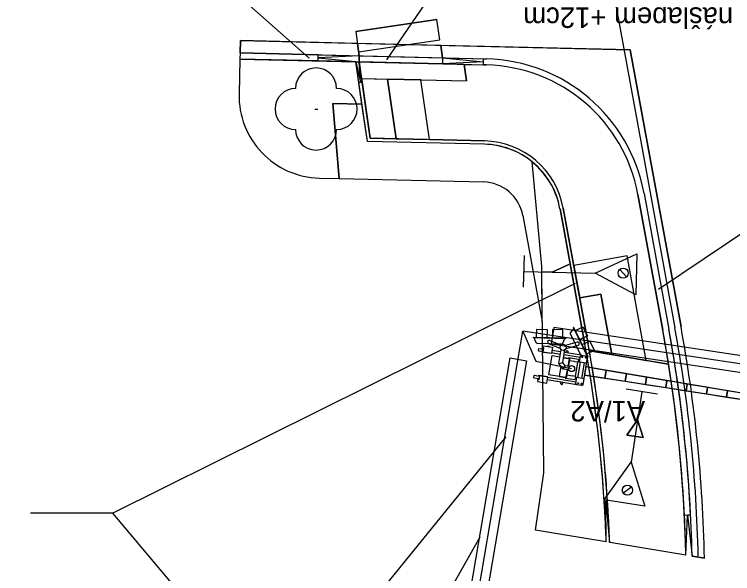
# Model space of a CAD drawing. Extents: x -728547 to -728179, y -1073068 to -1072839.
# Drawn here: x -728526.3 to -728508.81, y -1073041.79 to -1073028.16 of the extents above; entities that cross this region are included whole.
import ezdxf

# ---------------------------------------------------------------- set-up
doc = ezdxf.new("R2010")
doc.units = 0
for name, color, linetype in [('_NOR-návrh tenká', 7, 'Continuous'), ('_NOR-popis', 7, 'Continuous'), ('_NOR-VDZ', 7, 'Continuous'), ('_NOR-zrušit', 7, 'Continuous'), ('_NOR-šraf_+12', 7, 'Continuous'), ('_NOR-šraf_+6', 7, 'Continuous'), ('_NOR-šraf_bezbariéra', 7, 'Continuous'), ('_NOR-šraf_chodník', 7, 'Continuous'), ('_NOR-šraf_signální pás', 7, 'Continuous'), ('_NOR-šraf_varovný pás', 7, 'Continuous'), ('_NOR-šraf_vozovka', 7, 'Continuous'), ('_NOR-šraf_zeleň', 7, 'Continuous'), ('KOS_kabelová trasa', 7, 'Continuous'), ('KOS_kabelová trasa popis', 7, 'Continuous'), ('KOS_nové prvky PZZ', 7, 'Continuous'), ('KTA_PZZ rušené', 7, 'Continuous')]:
    doc.layers.add(name, color=color, linetype=linetype)

# ---------------------------------------------------------------- blocks, each defined once
blk = doc.blocks.new('Závora A')
for p, q in [((0.395, 0.28), (0.046, 0.997)), ((-0.139, 0.725), (-0.935, 0.747)), ((-0.596, 0.546), (-0.597, 0.54)), ((-0.535, 0.536), (-0.596, 0.546)), ((-0.563, 0.613), (-0.27, 0.487)), ((0.138, 0.645), (-0.147, 0.563)), ((-0.697, 0.505), (-0.702, 0.477)), ((-0.277, 0.347), (-0.486, 0.381)), ((-0.268, 0.407), (-0.477, 0.44)), ((0.244, 0.323), (-0.178, 0.392)), ((0.209, 0.268), (-0.188, 0.333)), ((0.191, 0.16), (0.215, 0.304)), ((0.244, 0.323), (0.215, 0.304)), ((0.279, -0.392), (0.387, 0.276)), ((0.365, 0.304), (0.387, 0.276)), ((-0.313, 0.128), (-0.217, 0.151)), ((-0.292, -0.182), (-0.255, 0.051)), ((-0.207, -0.012), (-0.156, 0.07)), ((0.094, -0.192), (0.15, 0.154)), ((0.153, -0.224), (0.215, 0.156)), ((0.364, 0.132), (0.191, 0.16)), ((0.253, -0.24), (0.314, 0.14)), ((0.349, 0.041), (0.317, -0.157)), ((0.349, 0.041), (0.317, -0.157)), ((0.349, 0.041), (0.317, -0.157)), ((0.349, 0.041), (0.317, -0.157)), ((7.251, -1.126), (0.349, 0.041)), ((7.234, -1.232), (0.317, -0.157)), ((-0.822, -0.267), (-0.818, -0.239)), ((-0.739, -0.338), (-0.738, -0.331)), ((-0.679, -0.347), (-0.739, -0.338)), ((0.128, -0.392), (-0.593, -0.275)), ((0.112, -0.329), (-0.583, -0.216)), ((0.302, -0.248), (0.13, -0.22)), ((0.128, -0.392), (0.106, -0.365)), ((0.249, -0.412), (0.128, -0.392)), ((0.249, -0.412), (0.279, -0.392)), ((7.251, -1.126), (7.234, -1.232))]:
    blk.add_line(p, q)
for points in [[(-0.856, 0.758), (-0.85, 0.96), (-0.599, 0.953), (-0.605, 0.751)], [(-0.217, 0.74), (-0.212, 0.942), (-0.463, 0.949), (-0.468, 0.747)], [(0.381, 0.307), (0.259, 0.299), (0.234, 0.31), (-0.029, 0.85), (-0.025, 0.875), (0.058, 0.972)], [(0.395, 0.28), (0.407, 0.286), (0.058, 1.002), (0.046, 0.997)], [(0.092, 0.931), (0.274, 1.02), (0.384, 0.794), (0.202, 0.706)], [(-0.139, 0.725), (-0.138, 0.738), (-0.935, 0.76), (-0.935, 0.747)], [(-0.169, 0.725), (-0.218, 0.613), (-0.24, 0.597), (-0.84, 0.613), (-0.86, 0.628), (-0.908, 0.746)], [(-0.465, 0.518), (-0.488, 0.371), (-0.691, 0.404), (-0.675, 0.502), (-0.697, 0.505), (-0.689, 0.555), (-0.465, 0.518)], [(-0.549, 0.689), (-0.561, 0.687), (-0.575, 0.676), (-0.581, 0.66), (-0.584, 0.646), (-0.582, 0.633), (-0.575, 0.623), (-0.573, 0.62), (-0.569, 0.617), (-0.563, 0.613)], [(-0.577, 0.536), (-0.536, 0.53)], [(-0.549, 0.689), (-0.257, 0.571)], [(-0.535, 0.536), (-0.536, 0.53)], [(0.159, 0.566), (-0.143, 0.48)], [(0.159, 0.566), (0.178, 0.576), (0.185, 0.588), (0.188, 0.603), (0.188, 0.619), (0.183, 0.629), (0.174, 0.636), (0.16, 0.643), (0.148, 0.644), (0.138, 0.645)], [(0.372, 0.357), (0.554, 0.446), (0.444, 0.671), (0.262, 0.583)], [(-0.804, 0.493), (-0.812, 0.44), (-0.807, 0.432), (-0.69, 0.413)], [(-0.804, 0.493), (-0.68, 0.473)], [(-0.691, 0.404), (-0.714, 0.408), (-0.712, 0.417)], [(-0.492, 0.372), (-0.493, 0.364), (-0.691, 0.396), (-0.69, 0.404)], [(-0.078, -0.033), (-0.207, -0.012), (-0.313, 0.128), (-0.258, 0.467)], [(-0.058, 0.054), (-0.156, 0.07), (-0.217, 0.151), (-0.168, 0.455)], [(-0.111, 0.433), (-0.124, 0.435), (-0.126, 0.428), (-0.13, 0.429), (-0.132, 0.42), (-0.136, 0.42), (-0.139, 0.397), (-0.148, 0.399), (-0.149, 0.393), (-0.15, 0.387)], [(-0.111, 0.433), (-0.098, 0.431), (-0.098, 0.424), (-0.094, 0.423), (-0.095, 0.414), (-0.092, 0.413), (-0.095, 0.39), (-0.087, 0.389), (-0.088, 0.383), (-0.089, 0.377)], [(-0.3, -0.193), (-0.552, -0.152), (-0.475, 0.319), (-0.287, 0.289)], [(-0.199, 0.263), (-0.072, 0.243), (-0.068, 0.24), (-0.065, 0.237), (-0.062, 0.232), (-0.061, 0.226), (-0.088, 0.059)], [(-0.197, 0.274), (-0.069, 0.253), (-0.059, 0.249), (-0.054, 0.243), (-0.049, 0.235), (-0.048, 0.231), (-0.076, 0.057)], [(-0.074, 0.268), (0.169, 0.228), (0.158, 0.16), (0.15, 0.154), (0.067, 0.167), (0.068, 0.17), (-0.048, 0.188), (-0.048, 0.192), (-0.054, 0.193)], [(0.244, 0.323), (0.365, 0.304)], [(-0.259, 0.057), (-0.3, -0.193)], [(0.349, 0.041), (0.317, -0.157), (0.811, -0.234), (0.842, -0.043), (0.349, 0.041)], [(-0.92, -0.222), (-0.911, -0.169), (-0.904, -0.163), (-0.786, -0.182)], [(-0.606, -0.353), (-0.582, -0.206), (-0.785, -0.173), (-0.801, -0.271), (-0.822, -0.267), (-0.83, -0.316), (-0.606, -0.353)], [(-0.785, -0.173), (-0.807, -0.17), (-0.809, -0.179)], [(-0.586, -0.206), (-0.584, -0.198), (-0.782, -0.166), (-0.783, -0.173)], [(-0.294, -0.193), (-0.292, -0.182), (-0.145, -0.206), (-0.14, -0.205), (-0.136, -0.203), (-0.132, -0.199), (-0.129, -0.194), (-0.103, -0.029)], [(-0.294, -0.193), (-0.145, -0.218), (-0.135, -0.217), (-0.128, -0.212), (-0.121, -0.207), (-0.118, -0.203), (-0.09, -0.031)], [(-0.155, -0.23), (0.089, -0.269), (0.1, -0.201), (0.094, -0.192), (0.011, -0.179), (0.011, -0.181), (-0.104, -0.163), (-0.106, -0.166), (-0.112, -0.165)], [(0.842, -0.043), (0.811, -0.234), (1.305, -0.31), (1.335, -0.126), (0.842, -0.043)], [(1.828, -0.209), (1.335, -0.126), (1.305, -0.31), (1.799, -0.387), (1.828, -0.209)], [(-0.92, -0.222), (-0.796, -0.242)], [(-0.718, -0.335), (-0.678, -0.341)], [(-0.679, -0.347), (-0.678, -0.341)], [(-0.243, -0.384), (-0.256, -0.381), (-0.256, -0.375), (-0.261, -0.374), (-0.259, -0.365), (-0.263, -0.364), (-0.259, -0.341), (-0.268, -0.34), (-0.267, -0.334), (-0.266, -0.328)], [(-0.243, -0.384), (-0.23, -0.386), (-0.228, -0.379), (-0.224, -0.38), (-0.222, -0.37), (-0.219, -0.371), (-0.215, -0.348), (-0.206, -0.35), (-0.206, -0.344), (-0.205, -0.338)], [(0.106, -0.365), (0.13, -0.22)], [(1.828, -0.209), (1.799, -0.387), (2.293, -0.464), (2.321, -0.293), (1.828, -0.209)], [(2.321, -0.293), (2.293, -0.464), (2.787, -0.541), (2.814, -0.376), (2.321, -0.293)], [(2.814, -0.376), (2.787, -0.541), (3.282, -0.618), (3.307, -0.459), (2.814, -0.376)], [(3.8, -0.543), (3.307, -0.459), (3.282, -0.618), (3.776, -0.694), (3.8, -0.543)], [(3.8, -0.543), (3.776, -0.694), (4.27, -0.771), (4.293, -0.626), (3.8, -0.543)], [(4.293, -0.626), (4.27, -0.771), (4.764, -0.848), (4.786, -0.709), (4.293, -0.626)], [(4.786, -0.709), (4.764, -0.848), (5.258, -0.925), (5.279, -0.793), (4.786, -0.709)], [(5.279, -0.793), (5.258, -0.925), (5.752, -1.001), (5.772, -0.876), (5.279, -0.793)], [(5.772, -0.876), (5.752, -1.001), (6.246, -1.078), (6.265, -0.959), (5.772, -0.876)], [(6.758, -1.043), (6.265, -0.959), (6.246, -1.078), (6.74, -1.155), (6.758, -1.043)], [(7.234, -1.232), (7.251, -1.126), (6.758, -1.043), (6.74, -1.155), (7.234, -1.232)]]:
    blk.add_lwpolyline(points)
for centre, radius in [((-0.206, 0.518), 0.0735), ((0.261, 0.282), 0.0119), ((0.343, 0.268), 0.0119), ((0, 0), 0.0742), ((0.157, -0.358), 0.0119), ((0.24, -0.371), 0.0119)]:
    blk.add_circle(centre, radius)
blk = doc.blocks.new('C039_9')
blk.add_line((-0.071, 0), (0.071, 0))
for centre, start, end in [((-0.011, 1.002), 0, 180), ((-1.011, 0.002), 90, 270), ((0.989, 0.002), 270, 90), ((-0.011, -0.998), 180, 0)]:
    blk.add_arc(centre, 1, start, end)

msp = doc.modelspace()

# ---------------------------------------------------------------- linework, layer by layer
at = {"layer": '_NOR-návrh tenká'}
for p, q in [((-728520.806, -1073029.105), (-728520.81, -1073029.255)), ((-728518.907, -1073029.3), (-728518.904, -1073029.151)), ((-728517.904, -1073029.174), (-728518.905, -1073029.225)), ((-728518.905, -1073029.225), (-728517.908, -1073029.324)), ((-728517.904, -1073029.174), (-728517.908, -1073029.324)), ((-728515.876, -1073029.222), (-728515.879, -1073029.372)), ((-728515.876, -1073029.222), (-728514.878, -1073029.321)), ((-728514.88, -1073029.396), (-728514.876, -1073029.246)), ((-728517.989, -1073029.322), (-728517.875, -1073029.825)), ((-728517.875, -1073029.825), (-728517.908, -1073029.324)), ((-728514.878, -1073029.321), (-728515.879, -1073029.372)), ((-728515.347, -1073029.385), (-728515.288, -1073029.787)), ((-728517.002, -1073031.196), (-728517.215, -1073029.741)), ((-728516.191, -1073031.215), (-728516.404, -1073029.76)), ((-728517.835, -1073029.819), (-728517.914, -1073029.831)), ((-728511.381, -1073034.047), (-728512.679, -1073034.285)), ((-728510.914, -1073036.596), (-728511.381, -1073034.047)), ((-728512.024, -1073034.978), (-728512.535, -1073035.072)), ((-728511.753, -1073036.454), (-728512.024, -1073034.978)), ((-728512.299, -1073036.362), (-728510.368, -1073036.688)), ((-728512.227, -1073036.779), (-728510.305, -1073037.104)), ((-728512.056, -1073038.959), (-728512.056, -1073038.959)), ((-728511.856, -1073040.029), (-728511.936, -1073040.035)), ((-728511.888, -1073041.015), (-728511.896, -1073040.032)), ((-728511.896, -1073040.032), (-728511.808, -1073041.028)), ((-728509.834, -1073040.364), (-728509.984, -1073040.371)), ((-728509.948, -1073041.338), (-728509.909, -1073040.368)), ((-728509.909, -1073040.368), (-728509.797, -1073041.363))]:
    msp.add_line(p, q, dxfattribs=at)
for points in [[(-728520.806, -1073029.105), (-728520.799, -1073028.805), (-728511.304, -1073029.031), (-728510.067, -1073035.777)], [(-728520.81, -1073029.255), (-728514.811, -1073029.398)], [(-728520.806, -1073029.105), (-728514.808, -1073029.248)], [(-728514.857, -1073031.327), (-728517.706, -1073031.26), (-728517.989, -1073029.322)], [(-728514.855, -1073031.247), (-728517.636, -1073031.181), (-728517.908, -1073029.324)], [(-728517.849, -1073029.726), (-728515.288, -1073029.787)], [(-728511.116, -1073032.553), (-728510.51, -1073035.858)], [(-728510.968, -1073032.525), (-728510.362, -1073035.831)], [(-728512.408, -1073036.206), (-728513.014, -1073032.9)], [(-728512.33, -1073036.192), (-728512.935, -1073032.886)], [(-728509.496, -1073041.413), (-728509.797, -1073041.363)]]:
    msp.add_lwpolyline(points, dxfattribs=at)
for centre, radius, start, end in [((-728514.903, -1073033.247), 4, 10.3872, 88.6393), ((-728514.903, -1073033.247), 3.85, 10.3872, 88.6393), ((-728514.903, -1073033.247), 1.92, 10.3872, 88.6393), ((-728514.903, -1073033.247), 2, 10.3872, 88.6393), ((-728544.789, -1073042.142), 34.85, 1.3216, 10.3872), ((-728544.789, -1073042.142), 35, 1.2748, 10.3872), ((-728544.789, -1073042.142), 35.3, 1.1826, 10.3872), ((-728544.789, -1073042.142), 32.92, 1.9617, 10.3872), ((-728544.789, -1073042.142), 33, 1.9337, 10.3872)]:
    msp.add_arc(centre, radius, start, end, dxfattribs=at)
at = {"layer": '_NOR-popis'}
for p, q in [((-728517.231, -1073029.269), (-728511.028, -1073020.188)), ((-728522.769, -1073026.006), (-728519.122, -1073029.229)), ((-728500.781, -1073028.245), (-728510.615, -1073034.866)), ((-728523.91, -1073040.313), (-728512.641, -1073034.717)), ((-728523.91, -1073040.313), (-728525.91, -1073040.313)), ((-728523.91, -1073040.313), (-728515.463, -1073050.376))]:
    msp.add_line(p, q, dxfattribs=at)
at = {"layer": '_NOR-VDZ'}
for p, q in [((-728517.991, -1073028.58), (-728516.012, -1073028.291)), ((-728517.919, -1073029.075), (-728515.939, -1073028.786))]:
    msp.add_line(p, q, dxfattribs=at)
for points in [[(-728512.949, -1073020.89), (-728510.942, -1073031.839)], [(-728517.919, -1073029.075), (-728515.939, -1073028.786), (-728516.012, -1073028.291), (-728517.991, -1073028.58), (-728517.919, -1073029.075), (-728517.919, -1073029.075)], [(-728510.942, -1073031.839), (-728510.215, -1073035.804)]]:
    msp.add_lwpolyline(points, dxfattribs=at)
msp.add_arc((-728544.789, -1073042.142), 35.15, 1.2748, 10.3872, dxfattribs=at)
at = {"layer": '_NOR-šraf_+12'}
for points in [[(-728520.81, -1073029.255), (-728518.907, -1073029.3), (-728518.905, -1073029.225), (-728518.904, -1073029.151), (-728520.806, -1073029.105), (-728520.81, -1073029.255)], [(-728514.88, -1073029.396), (-728514.878, -1073029.321), (-728514.876, -1073029.246), (-728514.808, -1073029.248)], [(-728514.811, -1073029.398), (-728514.88, -1073029.396)], [(-728510.51, -1073035.858), (-728511.116, -1073032.553)], [(-728510.968, -1073032.525), (-728510.362, -1073035.831)], [(-728509.834, -1073040.364), (-728509.909, -1073040.368), (-728509.984, -1073040.371)]]:
    msp.add_lwpolyline(points, dxfattribs=at)
for centre, radius, start, end in [((-728514.903, -1073033.247), 4, 10.3872, 88.6393), ((-728514.903, -1073033.247), 3.85, 10.3872, 88.6393), ((-728544.789, -1073042.142), 34.85, 2.9119, 10.3872), ((-728544.789, -1073042.142), 35, 2.9119, 10.3872)]:
    msp.add_arc(centre, radius, start, end, dxfattribs=at)
at = {"layer": '_NOR-šraf_+6'}
for points in [[(-728517.989, -1073029.322), (-728517.875, -1073029.825), (-728517.908, -1073029.324), (-728517.849, -1073029.726), (-728517.835, -1073029.819), (-728517.636, -1073031.181), (-728517.002, -1073031.196), (-728516.191, -1073031.215), (-728514.855, -1073031.247)], [(-728514.857, -1073031.327), (-728517.706, -1073031.26), (-728517.989, -1073029.322)], [(-728512.408, -1073036.206), (-728513.014, -1073032.9)], [(-728512.935, -1073032.886), (-728512.33, -1073036.192)], [(-728511.856, -1073040.029), (-728511.936, -1073040.035)]]:
    msp.add_lwpolyline(points, dxfattribs=at)
for centre, radius, start, end in [((-728514.903, -1073033.247), 1.92, 10.3872, 88.6393), ((-728514.903, -1073033.247), 2, 10.3872, 88.6393), ((-728544.789, -1073042.142), 32.92, 3.67, 10.3872), ((-728544.789, -1073042.142), 33, 3.67, 10.3872)]:
    msp.add_arc(centre, radius, start, end, dxfattribs=at)
at = {"layer": '_NOR-šraf_bezbariéra'}
msp.add_lwpolyline([(-728517.904, -1073029.174), (-728515.876, -1073029.222), (-728515.879, -1073029.372), (-728517.908, -1073029.324), (-728517.904, -1073029.174), (-728517.904, -1073029.174)], dxfattribs=at)
at = {"layer": '_NOR-šraf_chodník'}
for p, q in [((-728515.288, -1073029.787), (-728515.347, -1073029.385)), ((-728515.347, -1073029.385), (-728514.88, -1073029.396)), ((-728514.88, -1073029.396), (-728514.811, -1073029.398)), ((-728516.191, -1073031.215), (-728516.404, -1073029.76)), ((-728516.404, -1073029.76), (-728515.288, -1073029.787)), ((-728514.855, -1073031.247), (-728516.191, -1073031.215)), ((-728511.116, -1073032.553), (-728510.51, -1073035.858)), ((-728512.679, -1073034.285), (-728512.935, -1073032.886)), ((-728511.381, -1073034.047), (-728512.679, -1073034.285)), ((-728510.914, -1073036.596), (-728511.381, -1073034.047)), ((-728512.535, -1073035.072), (-728512.024, -1073034.978)), ((-728512.024, -1073034.978), (-728511.753, -1073036.454)), ((-728512.33, -1073036.192), (-728512.535, -1073035.072)), ((-728511.753, -1073036.454), (-728512.299, -1073036.362)), ((-728510.368, -1073036.688), (-728510.914, -1073036.596)), ((-728512.227, -1073036.779), (-728510.305, -1073037.104)), ((-728511.387, -1073038.413), (-728510.992, -1073038.473)), ((-728510.992, -1073038.473), (-728511.387, -1073038.413)), ((-728511.755, -1073041.037), (-728511.808, -1073041.028)), ((-728510.582, -1073041.232), (-728511.755, -1073041.037)), ((-728509.948, -1073041.338), (-728510.582, -1073041.232))]:
    msp.add_line(p, q, dxfattribs=at)
for points in [[(-728517.835, -1073029.819), (-728517.849, -1073029.726), (-728517.215, -1073029.741), (-728517.002, -1073031.196), (-728517.636, -1073031.181), (-728517.835, -1073029.819)], [(-728510.992, -1073038.473), (-728511.126, -1073038.046), (-728511.387, -1073038.413)], [(-728511.387, -1073038.413), (-728511.126, -1073038.046), (-728510.992, -1073038.473)]]:
    msp.add_lwpolyline(points, dxfattribs=at)
for centre, radius, start, end in [((-728514.903, -1073033.247), 3.85, 10.3872, 88.6393), ((-728514.903, -1073033.247), 2, 10.3872, 88.6393), ((-728544.789, -1073042.142), 34.85, 9.0036, 10.3872), ((-728544.789, -1073042.142), 33, 10.0878, 10.3872), ((-728544.789, -1073042.142), 33, 3.67, 9.3519), ((-728544.789, -1073042.142), 34.85, 2.9119, 8.3112), ((-728544.789, -1073042.142), 33, 1.9337, 3.67), ((-728544.789, -1073042.142), 34.85, 1.3216, 2.9119)]:
    msp.add_arc(centre, radius, start, end, dxfattribs=at)
at = {"layer": '_NOR-šraf_signální pás'}
for points in [[(-728517.002, -1073031.196), (-728516.191, -1073031.215), (-728516.404, -1073029.76), (-728517.215, -1073029.741), (-728517.002, -1073031.196)], [(-728512.535, -1073035.072), (-728512.024, -1073034.978), (-728511.753, -1073036.454), (-728510.914, -1073036.596), (-728511.381, -1073034.047), (-728512.679, -1073034.285), (-728512.535, -1073035.072)]]:
    msp.add_lwpolyline(points, dxfattribs=at)
at = {"layer": '_NOR-šraf_varovný pás'}
msp.add_line((-728512.227, -1073036.779), (-728510.305, -1073037.104), dxfattribs=at)
for points in [[(-728517.849, -1073029.726), (-728517.215, -1073029.741), (-728516.404, -1073029.76), (-728515.288, -1073029.787), (-728515.347, -1073029.385), (-728515.879, -1073029.372), (-728517.908, -1073029.324), (-728517.849, -1073029.726)], [(-728510.368, -1073036.688), (-728510.914, -1073036.596), (-728511.753, -1073036.454), (-728512.299, -1073036.362)]]:
    msp.add_lwpolyline(points, dxfattribs=at)
for radius, start, end in [(33, 9.3519, 10.0878), (34.85, 8.3112, 9.0036)]:
    msp.add_arc((-728544.789, -1073042.142), radius, start, end, dxfattribs=at)
at = {"layer": '_NOR-šraf_vozovka'}
for p, q in [((-728510.968, -1073032.525), (-728510.362, -1073035.831)), ((-728509.797, -1073041.363), (-728509.496, -1073041.413))]:
    msp.add_line(p, q, dxfattribs=at)
for points in [[(-728517.904, -1073029.174), (-728517.948, -1073028.873), (-728520.799, -1073028.805), (-728520.806, -1073029.105), (-728518.904, -1073029.151), (-728517.904, -1073029.174)], [(-728515.876, -1073029.222), (-728515.92, -1073028.921), (-728517.948, -1073028.873), (-728517.904, -1073029.174), (-728515.876, -1073029.222)], [(-728510.067, -1073035.777), (-728511.304, -1073029.031), (-728515.92, -1073028.921), (-728515.876, -1073029.222), (-728514.808, -1073029.248)]]:
    msp.add_lwpolyline(points, dxfattribs=at)
for centre, radius, start, end in [((-728514.903, -1073033.247), 4, 10.3872, 88.6393), ((-728544.789, -1073042.142), 35, 1.2748, 10.3872), ((-728544.789, -1073042.142), 35.3, 1.1826, 10.3872)]:
    msp.add_arc(centre, radius, start, end, dxfattribs=at)
at = {"layer": '_NOR-šraf_zeleň'}
for p, q in [((-728517.838, -1073030.354), (-728518.545, -1073030.338)), ((-728518.545, -1073030.338), (-728518.39, -1073032.164)), ((-728517.706, -1073031.26), (-728517.838, -1073030.354)), ((-728514.857, -1073031.327), (-728517.706, -1073031.26)), ((-728513.46, -1073034.306), (-728513.69, -1073031.758)), ((-728518.39, -1073032.164), (-728514.879, -1073032.247)), ((-728513.919, -1073033.066), (-728513.447, -1073035.644)), ((-728513.447, -1073035.644), (-728513.46, -1073034.306))]:
    msp.add_line(p, q, dxfattribs=at)
for points in [[(-728518.878, -1073032.152), (-728518.39, -1073032.164), (-728518.545, -1073030.338), (-728517.838, -1073030.354), (-728517.989, -1073029.322), (-728518.907, -1073029.3), (-728520.81, -1073029.255), (-728520.83, -1073030.105), (-728520.83, -1073030.105)], [(-728513.459, -1073034.436), (-728513.202, -1073034.442), (-728512.796, -1073034.255), (-728513.202, -1073034.442), (-728513.459, -1073034.436), (-728513.46, -1073034.306), (-728513.69, -1073031.758)], [(-728513.014, -1073032.9), (-728512.408, -1073036.206)], [(-728511.888, -1073041.015), (-728512.928, -1073040.842), (-728513.61, -1073040.728), (-728513.41, -1073039.33), (-728513.459, -1073034.436)]]:
    msp.add_lwpolyline(points, dxfattribs=at)
for centre, radius, start, end in [((-728518.83, -1073030.153), 2, 178.6393, 268.6393), ((-728514.903, -1073033.247), 1.92, 50.8365, 88.6393), ((-728514.903, -1073033.247), 1.92, 10.3872, 50.8365), ((-728514.903, -1073033.247), 1, 10.3872, 88.6393), ((-728544.789, -1073042.142), 32.92, 3.67, 10.3872), ((-728544.789, -1073042.142), 32.92, 1.9617, 3.67)]:
    msp.add_arc(centre, radius, start, end, dxfattribs=at)
at = {"layer": 'KOS_kabelová trasa'}
for points in [[(-728513.395, -1073046.387), (-728515.647, -1073046.052), (-728513.917, -1073035.879)], [(-728513.917, -1073035.879), (-728513.6, -1073036.611), (-728512.732, -1073036.794)], [(-728494.829, -1073039.422), (-728494.767, -1073038.764), (-728513.916, -1073035.879)], [(-728495.471, -1073038.866), (-728495.411, -1073038.47), (-728513.167, -1073035.794), (-728513.227, -1073036.19), (-728495.471, -1073038.866)], [(-728515.318, -1073045.332), (-728515.712, -1073045.265), (-728514.228, -1073036.535), (-728513.834, -1073036.602), (-728515.318, -1073045.332)]]:
    msp.add_lwpolyline(points, dxfattribs=at)
at = {"layer": 'KOS_kabelová trasa popis'}
for p, q in [((-728527.449, -1073054.604), (-728514.328, -1073038.456)), ((-728514.97, -1073040.9), (-728525.475, -1073059.597))]:
    msp.add_line(p, q, dxfattribs=at)
at = {"layer": 'KTA_PZZ rušené'}
for p, q in [((-728513.886, -1073034.036), (-728513.908, -1073034.814)), ((-728511.56, -1073034.38), (-728511.393, -1073034.559)), ((-728510.637, -1073037.419), (-728511.405, -1073037.299)), ((-728511.273, -1073039.682), (-728511.472, -1073039.826))]:
    msp.add_line(p, q, dxfattribs=at)
for points in [[(-728513.897, -1073034.425), (-728512.159, -1073034.468), (-728511.144, -1073033.999), (-728511.166, -1073034.998), (-728512.159, -1073034.468)], [(-728511.021, -1073037.359), (-728511.284, -1073039.077), (-728510.949, -1073040.144), (-728511.936, -1073039.995), (-728511.284, -1073039.077)]]:
    msp.add_lwpolyline(points, dxfattribs=at)
for centre in [(-728511.477, -1073034.469), (-728511.477, -1073034.469), (-728511.373, -1073039.754), (-728511.373, -1073039.754)]:
    msp.add_circle(centre, 0.124, dxfattribs=at)

# ---------------------------------------------------------------- block references
at = {"layer": '_NOR-zrušit', "xscale": 0.5, "yscale": 0.5}
msp.add_blockref('C039_9', (-728518.95, -1073030.471), dxfattribs=at)
at = {"layer": 'KOS_nové prvky PZZ'}
msp.add_blockref('Závora A', (-728512.732, -1073036.794), dxfattribs=at)

# ---------------------------------------------------------------- texts
at = {"layer": '_NOR-popis'}
msp.add_text('silniční obruba s nášlapem +12cm', height=0.5, rotation=180, dxfattribs=at).set_placement((-728503.781, -1073027.995))
at = {"layer": 'KOS_nové prvky PZZ'}
msp.add_text('A1/A2', height=0.5, rotation=180, dxfattribs=at).set_placement((-728510.941, -1073037.582))

doc.saveas('drawing.dxf')
